// Mitsubishi GX Works2 project: 20.顺序控制的分支与回合（2）   PLC: FX3U/FX3UC

PROGRAM MAIN
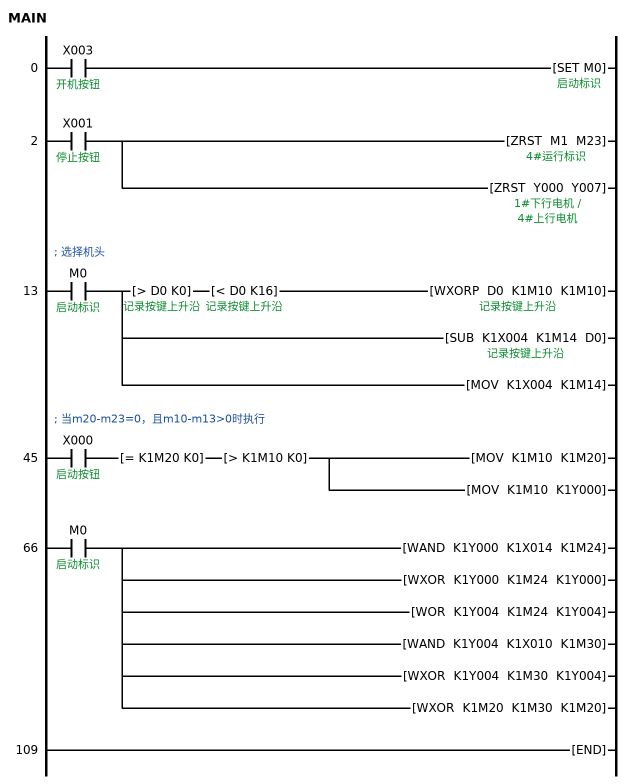
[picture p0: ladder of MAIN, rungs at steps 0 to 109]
0     LD      X003  ; 开机按钮
      SET     M0  ; 启动标识
2     LD      X001  ; 停止按钮
      ZRST    M1 M23  ; 4#运行标识
      ZRST    Y000 Y007  ; 1#下行电机 / 4#上行电机
; 选择机头
13    LD      M0  ; 启动标识
      MPS
      AND>    D0 K0  ; 记录按键上升沿
      AND<    D0 K16  ; 记录按键上升沿
      WXORP   D0 K1M10 K1M10  ; 机头选择标识
        [note] 各个按钮分别设置各自的电机
      MPP
      SUB     K1X004 K1M14 D0  ; 按下新按键前的状态
      MOV     K1X004 K1M14
        [note] 寄存按下X4-X7前的状态
; 当m20-m23=0，且m10-m13>0时执行
45    LD      X000  ; 启动按钮
      AND=    K1M20 K0  ; 机头运行标识
      AND>    K1M10 K0  ; 机头选择标识
      MOV     K1M10 K1M20
        [note] 把m10-m13转到m20-m23
      MOV     K1M10 K1Y000
        [note] 按机头选择启动下行电机
66    LD      M0  ; 启动标识
      WAND    K1Y000 K1X014 K1M24  ; 1#下限位 / 得出下行到位情况
        [note] Y0-Y4下行到达限位时寄存到M24-M27
      WXOR    K1Y000 K1M24 K1Y000
        [note] 下行到位的停止，未到位的继续下行
      WOR     K1Y004 K1M24 K1Y004  ; 1#上行电机
        [note] 下行到位的开始上行，未到的继续
      WAND    K1Y004 K1X010 K1M30  ; 1#上限位 / 得出上行到位情况
        [note] Y4-Y7上行到达限位时寄存到M30-M33
      WXOR    K1Y004 K1M30 K1Y004
        [note] 上行到位的停止，未到位的继续上行
      WXOR    K1M20 K1M30 K1M20
        [note] 已到位的机头进入准备状态
109   END
END_PROGRAM

// device comments not shown above
X011  ; 2#上限位
X012  ; 3#上限位
X013  ; 4#上限位
X015  ; 2#下限位
X016  ; 3#下限位
X017  ; 4#下限位
Y001  ; 2#下行电机
Y002  ; 3#下行电机
Y003  ; 4#下行电机
Y005  ; 2#上行电机
Y006  ; 3#上行电机
M11  ; 2#机头标识
M12  ; 3#机头标识
M13  ; 4#机头标识
M21  ; 2#运行标识
M22  ; 3#运行标识
D1  ; 寄存选择标识状态
D500  ; 1#步骤数
D501  ; 2#步骤数
D502  ; 3#步骤数
D503  ; 4#步骤数
